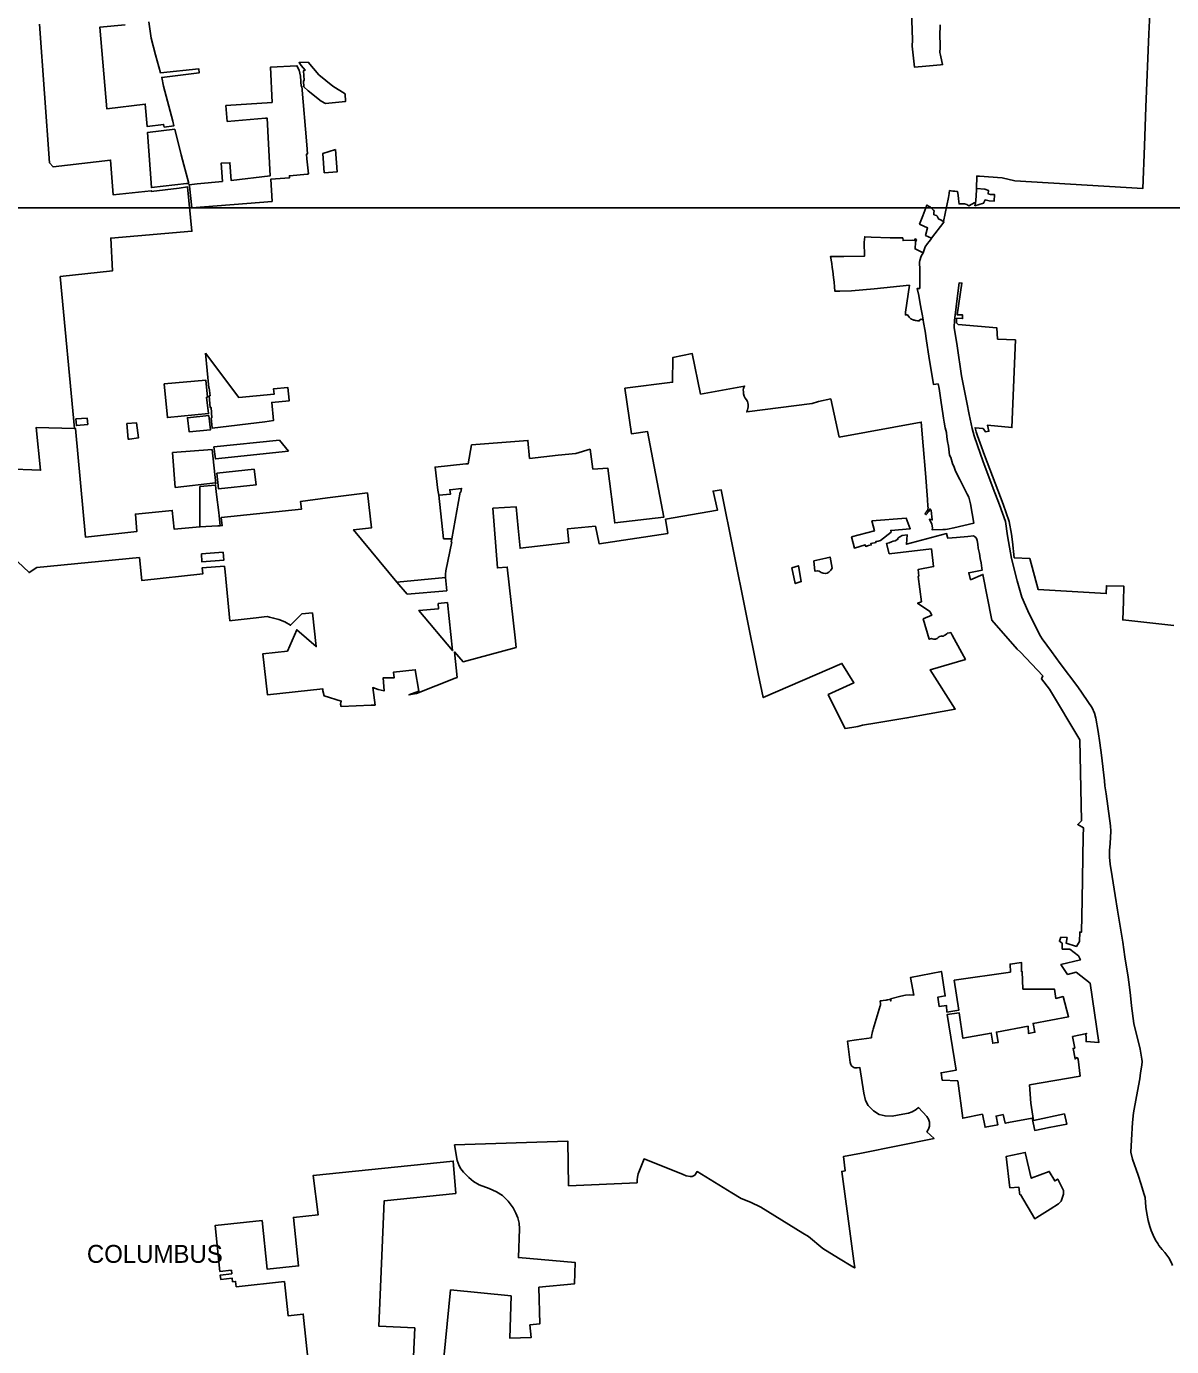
# Model space of a CAD drawing. Extents: x 1674899 to 2057726, y 653888 to 988278.
# Drawn here: x 1771787 to 1803723, y 730859 to 767682 of the extents above; entities that cross this region are included whole.
import ezdxf

# ---------------------------------------------------------------- set-up
doc = ezdxf.new("R2010")
doc.units = 0
for name, color, linetype in [('GM_X_Corporation', 7, 'Continuous'), ('GM_X_Corporation_Text', 7, 'Continuous'), ('SH_Named_Boundary', 7, 'Continuous')]:
    doc.layers.add(name, color=color, linetype=linetype)

msp = doc.modelspace()

# ---------------------------------------------------------------- linework, layer by layer
at = {"layer": 'GM_X_Corporation'}
for points in [[(1770221, 755380), (1772181, 755302), (1772057, 756492), (1773124, 756470), (1773153, 756469), (1773437, 753432), (1774866, 753591), (1774825, 754079), (1775856, 754180), (1775906, 753660), (1776624, 753722), (1777130, 753751), (1777182, 753756), (1777187, 753756), (1777192, 753756), (1777203, 753757), (1777227, 753759), (1777248, 753761), (1777222, 753980), (1779459, 754220), (1779429, 754427), (1780187, 754529), (1781295, 754669), (1781415, 753697), (1780909, 753642), (1782119, 752179), (1782408, 751849), (1783508, 751942), (1783479, 752309), (1783471, 752408), (1783484, 752497), (1783649, 753302), (1783633, 753301), (1783649, 753390), (1783882, 754688), (1783903, 754693), (1783921, 754795), (1783593, 754757), (1783615, 754639), (1783284, 754607), (1783265, 754751), (1783184, 755392), (1784040, 755478), (1784107, 755485), (1784200, 756011), (1785774, 756133), (1785821, 755634), (1786620, 755722), (1787106, 755772), (1787508, 755887), (1787585, 755334), (1787998, 755364), (1788193, 753835), (1789563, 753993), (1789108, 756382), (1788659, 756318), (1788479, 757590), (1789807, 757755), (1789818, 758450), (1790355, 758555), (1790586, 757428), (1791817, 757651), (1791798, 757614), (1791788, 757587), (1791780, 757546), (1791782, 757487), (1791788, 757438), (1791805, 757364), (1791835, 757312), (1791867, 757269), (1791892, 757218), (1791908, 757179), (1791915, 757135), (1791911, 757075), (1791904, 757024), (1791892, 756983), (1791876, 756928), (1793703, 757167), (1793873, 757222), (1794220, 757291), (1794455, 756226), (1796742, 756644), (1796798, 755979), (1796859, 755222), (1796915, 754482), (1796927, 754304), (1796931, 754250), (1796929, 754213), (1796912, 754181), (1796877, 754133), (1796843, 754097), (1796883, 754064), (1796952, 754150), (1796983, 754223), (1797022, 754175), (1797047, 753919), (1796968, 753934), (1797035, 753796), (1797053, 753693), (1797049, 753638), (1797341, 753647), (1797421, 753653), (1797474, 753661), (1797655, 753696), (1798210, 753829), (1798116, 754362), (1798071, 754553), (1798026, 754636), (1797814, 755043), (1797693, 755276), (1797657, 755384), (1797616, 755493), (1797564, 755654), (1797534, 755727), (1797500, 755975), (1797475, 756104), (1797452, 756237), (1797445, 756358), (1797413, 756483), (1797382, 756639), (1797361, 756753), (1797349, 756823), (1797285, 757257), (1797242, 757581), (1797210, 757710), (1797087, 757691), (1796955, 758481), (1796885, 758915), (1796847, 759179), (1796806, 759422), (1796792, 759498), (1796775, 759605), (1796742, 759796), (1796699, 760004), (1796671, 760173), (1796631, 760376), (1796701, 760373), (1796705, 760456), (1796703, 760557), (1796705, 760694), (1796699, 760891), (1796690, 761106), (1796705, 761148), (1796741, 761269), (1796792, 761362), (1796847, 761530), (1796917, 761623), (1796961, 761681), (1797003, 761733), (1797028, 761773), (1797374, 762223), (1797363, 762240), (1797453, 762684), (1797500, 762912), (1797522, 763017), (1797533, 763101), (1797623, 763091), (1797676, 763083), (1797721, 763081), (1797757, 763077), (1797761, 763030), (1797770, 762968), (1797782, 762885), (1797788, 762787), (1797797, 762730), (1797881, 762730), (1797948, 762730), (1798010, 762716), (1798071, 762682), (1798232, 762768), (1798251, 762763), (1798259, 762760), (1798240, 762681), (1798478, 762748), (1798523, 762842), (1798636, 762814), (1798776, 762808), (1798789, 762992), (1798672, 762998), (1798612, 763008), (1798618, 763105), (1798514, 763138), (1798285, 763163), (1798291, 763505), (1798362, 763501), (1799001, 763458), (1799354, 763375), (1802922, 763165), (1802964, 764353), (1803002, 765433), (1803091, 767476), (1803123, 768218)], [(1803123, 768218), (1803091, 767476), (1803002, 765433), (1802964, 764353), (1802922, 763165), (1799354, 763375), (1799001, 763458), (1798362, 763501), (1798291, 763505), (1798285, 763163), (1798285, 763121), (1798261, 762817), (1798251, 762763), (1798232, 762768), (1798071, 762682), (1798010, 762716), (1797948, 762730), (1797881, 762730), (1797797, 762730), (1797788, 762787), (1797782, 762885), (1797770, 762968), (1797761, 763030), (1797757, 763077), (1797721, 763081), (1797676, 763083), (1797623, 763091), (1797533, 763101), (1797522, 763017), (1797500, 762912), (1797453, 762684), (1797363, 762240), (1797328, 762261), (1797285, 762286), (1797235, 762306), (1797215, 762337), (1797189, 762393), (1797166, 762407), (1797095, 762431), (1797095, 762464), (1797096, 762492), (1797098, 762526), (1797079, 762553), (1797035, 762603), (1796999, 762638), (1796960, 762661), (1796901, 762700), (1796787, 762397), (1796734, 762256), (1796695, 762167), (1796714, 762158), (1796917, 762062), (1796864, 761847), (1797028, 761773), (1797003, 761733), (1796961, 761681), (1796917, 761623), (1796847, 761530), (1796792, 761362), (1796570, 761475), (1796586, 761667), (1796609, 761738), (1796566, 761754), (1796559, 761715), (1796509, 761719), (1796236, 761708), (1796228, 761782), (1795879, 761782), (1795343, 761802), (1795167, 761813), (1795148, 761662), (1795159, 761273), (1794583, 761261), (1794207, 761261), (1794244, 761065), (1794262, 760959), (1794275, 760853), (1794298, 760683), (1794310, 760545), (1794319, 760417), (1794336, 760293), (1794473, 760293), (1794798, 760307), (1795429, 760358), (1796412, 760460), (1796307, 759710), (1796302, 759633), (1796357, 759638), (1796408, 759574), (1796455, 759524), (1796534, 759493), (1796552, 759487), (1796578, 759477), (1796599, 759476), (1796640, 759471), (1796685, 759467), (1796706, 759495), (1796737, 759516), (1796763, 759510), (1796792, 759498), (1796806, 759422), (1796847, 759179), (1796885, 758915), (1796955, 758481), (1797087, 757691), (1797210, 757710), (1797242, 757581), (1797285, 757257), (1797349, 756823), (1797361, 756753), (1797382, 756639), (1797413, 756483), (1797445, 756358), (1797452, 756237), (1797475, 756104), (1797500, 755975), (1797534, 755727), (1797564, 755654), (1797616, 755493), (1797657, 755384), (1797693, 755276), (1797814, 755043), (1798026, 754636), (1798071, 754553), (1798116, 754362), (1798210, 753829), (1797655, 753696), (1797474, 753661), (1797421, 753653), (1797341, 753647), (1797049, 753638), (1797053, 753693), (1797035, 753796), (1796968, 753934), (1797047, 753919), (1797022, 754175), (1796983, 754223), (1796952, 754150), (1796883, 754064), (1796843, 754097), (1796877, 754133), (1796912, 754181), (1796929, 754213), (1796931, 754250), (1796927, 754304), (1796915, 754482), (1796859, 755222), (1796798, 755979), (1796742, 756644), (1794455, 756226), (1794220, 757291), (1793873, 757222), (1793703, 757167), (1791876, 756928), (1791892, 756983), (1791904, 757024), (1791911, 757075), (1791915, 757135), (1791908, 757179), (1791892, 757218), (1791867, 757269), (1791835, 757312), (1791805, 757364), (1791788, 757438), (1791782, 757487), (1791780, 757546), (1791788, 757587), (1791798, 757614), (1791817, 757651), (1790586, 757428), (1790355, 758555), (1789818, 758450), (1789807, 757755), (1788479, 757590), (1788659, 756318), (1789108, 756382), (1789563, 753993), (1788193, 753835), (1787998, 755364), (1787585, 755334), (1787508, 755887), (1787106, 755772), (1786620, 755722), (1785821, 755634), (1785774, 756133), (1784200, 756011), (1784107, 755485), (1784040, 755478), (1783184, 755392), (1783265, 754751), (1783284, 754607), (1783421, 753391), (1783649, 753390), (1783633, 753301), (1783649, 753302), (1783484, 752497), (1783471, 752408), (1783479, 752309), (1782119, 752179), (1780909, 753642), (1781415, 753697), (1781295, 754669), (1780187, 754529), (1779429, 754427), (1779459, 754220), (1777222, 753980), (1777248, 753761), (1777227, 753759), (1777203, 753757), (1777192, 753756), (1777150, 754125), (1777091, 754630), (1777072, 754794), (1777061, 754886), (1776626, 754848), (1776624, 753722), (1775906, 753660), (1775856, 754180), (1774825, 754079), (1774866, 753591), (1773437, 753432), (1773153, 756469), (1773124, 756470), (1772730, 760702), (1774189, 760869), (1774141, 761779), (1776402, 761968), (1776281, 763207), (1776046, 763174), (1775267, 763080), (1775267, 763099), (1774207, 762980), (1774134, 763952), (1772529, 763765), (1772435, 763880), (1772154, 767744)], [(1796465, 768373), (1796499, 767312), (1796490, 767130), (1796555, 766544), (1796870, 766570), (1797279, 766609), (1797338, 766615), (1797312, 766701), (1797277, 766882), (1797259, 766955), (1797271, 767095), (1797270, 767147), (1797268, 767221), (1797269, 767275), (1797264, 767337), (1797264, 767536), (1797272, 767608), (1797272, 767726)], [(1774541, 767725), (1773835, 767662), (1774031, 765380), (1775103, 765517), (1775155, 764887), (1775613, 764948), (1775632, 764875), (1775901, 764913), (1775868, 765038), (1775612, 766018), (1775562, 766261), (1776602, 766385), (1776595, 766499), (1775530, 766385), (1775389, 766892), (1775267, 767351), (1775201, 767808)], [(1803782, 750969), (1802362, 751127), (1802386, 751643), (1802395, 752068), (1801904, 752081), (1801902, 751864), (1800004, 751976), (1799768, 752839), (1799337, 752860), (1799288, 753301), (1799259, 753517), (1799195, 753873), (1799030, 754356), (1798507, 755721), (1798384, 756061), (1798314, 756259), (1798276, 756372), (1798244, 756489), (1798467, 756467), (1798529, 756374), (1798628, 756388), (1798591, 756564), (1799270, 756493), (1799367, 758939), (1798870, 758963), (1798849, 759277), (1797769, 759368), (1797722, 759416), (1797725, 759540), (1797893, 759534), (1797896, 759634), (1797741, 759640), (1797877, 760524), (1797803, 760530), (1797766, 760246), (1797665, 759477), (1797660, 759284), (1797739, 758775), (1797865, 757935), (1798015, 757195), (1798077, 756860), (1798161, 756466), (1798219, 756258), (1798311, 755995), (1798463, 755566), (1798749, 754795), (1798922, 754336), (1799095, 753877), (1799143, 753477), (1799257, 752840), (1799415, 752215), (1799549, 751765), (1799716, 751380), (1799745, 751315), (1800064, 750675), (1800110, 750597), (1800378, 750247), (1800618, 749910), (1801104, 749259), (1801506, 748678), (1801573, 748527), (1801614, 748387), (1801674, 748018), (1801725, 747703), (1801772, 747359), (1801849, 746636), (1801866, 746504), (1801900, 746273), (1801946, 745930), (1802019, 745382), (1802026, 745240), (1802006, 744894), (1801995, 744699), (1801990, 744508), (1802010, 744316), (1802068, 743972), (1802151, 743437), (1802219, 743032), (1802361, 742140), (1802422, 741731), (1802510, 741161), (1802552, 740884), (1802579, 740653), (1802606, 740359), (1802669, 739874), (1802844, 739158), (1802892, 738875), (1802901, 738809), (1802896, 738710), (1802860, 738491), (1802839, 738324), (1802746, 737839), (1802664, 737376), (1802630, 737112), (1802604, 736629), (1802584, 736279), (1802630, 736088), (1802792, 735637), (1802877, 735381), (1802950, 735133), (1802983, 735015), (1803009, 734748), (1803029, 734574), (1803069, 734376), (1803118, 734213), (1803153, 734096), (1803206, 733969), (1803274, 733830), (1803337, 733732), (1803368, 733683), (1803458, 733568), (1803531, 733484), (1803645, 733338), (1803723, 733195), (1803753, 733119)], [(1783429, 730546), (1783614, 732439), (1785305, 732274), (1785265, 731095), (1785864, 731116), (1785829, 731462), (1786109, 731495), (1786081, 732516), (1787068, 732606), (1787086, 733205), (1785506, 733341), (1785537, 734146), (1785530, 734302), (1785490, 734451), (1785435, 734577), (1785357, 734729), (1785223, 734911), (1785067, 735075), (1784895, 735179), (1784693, 735269), (1784413, 735373), (1784257, 735460), (1784128, 735574), (1784041, 735657), (1783980, 735727), (1783903, 735814), (1783857, 735903), (1783797, 736047), (1783729, 736484), (1786883, 736592), (1786907, 735343), (1788818, 735431), (1788815, 735475), (1788820, 735508), (1788829, 735580), (1788851, 735682), (1788920, 735864), (1789012, 736092), (1790098, 735655), (1790189, 735623), (1790305, 735599), (1790352, 735602), (1790432, 735643), (1790492, 735739), (1791458, 735151), (1791718, 734992), (1791982, 734884), (1792270, 734745), (1793442, 734023), (1793602, 733927), (1793997, 733597), (1794437, 733326), (1794832, 733084), (1794885, 733054), (1794861, 733242), (1794699, 734497), (1794545, 735602), (1794525, 735745), (1794624, 735763), (1794570, 736161), (1795072, 736254), (1797098, 736664), (1796898, 736851), (1796940, 736926), (1796970, 737010), (1796975, 737119), (1796947, 737199), (1796900, 737273), (1796669, 737527), (1796601, 737474), (1796487, 737408), (1796389, 737373), (1796226, 737341), (1795929, 737286), (1795732, 737292), (1795571, 737335), (1795407, 737432), (1795257, 737587), (1795185, 737723), (1795137, 737924), (1795029, 738645), (1794951, 738634), (1794915, 738633), (1794889, 738637), (1794863, 738646), (1794833, 738663), (1794810, 738682), (1794791, 738704), (1794776, 738730), (1794767, 738751), (1794761, 738782), (1794687, 739379), (1794932, 739413), (1795353, 739472), (1795356, 739509), (1795364, 739564), (1795371, 739604), (1795380, 739643), (1795389, 739677), (1795400, 739714), (1795598, 740361), (1795600, 740370), (1795602, 740377), (1795603, 740384), (1795604, 740394), (1795605, 740401), (1795605, 740409), (1795604, 740415), (1795603, 740425), (1795596, 740483), (1795595, 740488), (1795593, 740491), (1795622, 740496), (1795614, 740501), (1795603, 740504), (1795756, 740523), (1795769, 740526), (1795782, 740529), (1795795, 740531), (1795811, 740534), (1795843, 740540), (1795853, 740541), (1795862, 740540), (1795869, 740537), (1795876, 740533), (1795883, 740527), (1795887, 740521), (1795889, 740516), (1795892, 740494), (1795895, 740520), (1795894, 740530), (1795892, 740542), (1795888, 740563), (1796176, 740637), (1796307, 740663), (1796408, 740671), (1796532, 740659), (1796442, 741158), (1797302, 741323), (1797412, 740638), (1797207, 740606), (1797242, 740342), (1797444, 740374), (1797459, 740191), (1797786, 740238), (1797664, 741078), (1799228, 741305), (1799220, 741530), (1799534, 741576), (1799542, 741316), (1799558, 741318), (1799575, 740830), (1800457, 740830), (1800493, 740571), (1800699, 740622), (1800850, 740057), (1799860, 739872), (1799911, 739627), (1799731, 739593), (1799723, 739796), (1798839, 739630), (1798886, 739338), (1798799, 739334), (1798737, 739318), (1798692, 739605), (1797903, 739457), (1797796, 740170), (1797469, 740123), (1797713, 738565), (1797296, 738495), (1797323, 738291), (1797759, 738271), (1797898, 737226), (1798449, 737341), (1798524, 736975), (1798882, 737045), (1798827, 737288), (1799026, 737330), (1799082, 737088), (1799179, 737105), (1799836, 737231), (1799906, 736887), (1800305, 736970), (1800508, 737011), (1800801, 737062), (1800735, 737351), (1799874, 737168), (1799795, 737644), (1799761, 738159), (1801173, 738406), (1801119, 738880), (1801089, 738921), (1801071, 738909), (1801032, 738885), (1800975, 739174), (1801024, 739183), (1800963, 739506), (1801356, 739592), (1801351, 739589), (1801346, 739585), (1801343, 739582), (1801339, 739577), (1801335, 739571), (1801333, 739567), (1801331, 739562), (1801330, 739557), (1801329, 739549), (1801329, 739546), (1801330, 739540), (1801331, 739535), (1801332, 739530), (1801335, 739524), (1801342, 739514), (1801343, 739495), (1801345, 739462), (1801344, 739422), (1801342, 739404), (1801341, 739386), (1801338, 739365), (1801694, 739338), (1801449, 740993), (1801066, 741306), (1800821, 741241), (1800636, 741516), (1801179, 741642), (1801130, 741758), (1800882, 741940), (1800674, 741946), (1800674, 742111), (1800596, 742166), (1800636, 742276), (1800810, 742267), (1800786, 742107), (1801071, 742020), (1801125, 742113), (1801155, 742156), (1801160, 742422), (1801214, 742421), (1801229, 743323), (1801259, 745100), (1801263, 745329), (1801105, 745419), (1801209, 745526), (1801161, 747779), (1800318, 749198), (1800097, 749485), (1800128, 749567), (1799507, 750229), (1799412, 750316), (1798706, 751120), (1798462, 752398), (1798117, 752249), (1798068, 752442), (1798442, 752517), (1798433, 752573), (1798413, 752720), (1798384, 752837), (1798362, 752976), (1798333, 753132), (1798318, 753240), (1798305, 753344), (1798285, 753395), (1798262, 753427), (1798227, 753454), (1798198, 753471), (1798041, 753453), (1797723, 753424), (1797479, 753412), (1797476, 753439), (1797450, 753537), (1796330, 753237), (1796353, 753497), (1796210, 753481), (1796143, 753449), (1796092, 753406), (1796093, 753377), (1796014, 753336), (1795954, 753326), (1795913, 753303), (1795847, 753280), (1795773, 753260), (1795848, 752973), (1797026, 753110), (1797087, 752615), (1796652, 752533), (1796671, 752350), (1796658, 752339), (1796746, 751636), (1796638, 751592), (1796977, 751366), (1797033, 751257), (1796799, 751155), (1796966, 750588), (1797025, 750609), (1797047, 750598), (1797092, 750589), (1797136, 750587), (1797160, 750598), (1797188, 750613), (1797217, 750636), (1797237, 750657), (1797253, 750666), (1797285, 750676), (1797298, 750681), (1797320, 750675), (1797341, 750673), (1797359, 750677), (1797381, 750690), (1797421, 750713), (1797454, 750740), (1797471, 750760), (1797531, 750772), (1797564, 750776), (1797603, 750700), (1797878, 750206), (1797975, 750025), (1796995, 749737), (1797690, 748639), (1796961, 748506), (1796340, 748394), (1795502, 748255), (1795107, 748192), (1794974, 748159), (1794804, 748124), (1794616, 748095), (1794574, 748180), (1794147, 749043), (1794865, 749373), (1794531, 749912), (1792336, 748961), (1792198, 749626), (1791164, 754755), (1790938, 754719), (1791056, 754185), (1789610, 753934), (1789671, 753539), (1787760, 753249), (1787654, 753742), (1786874, 753665), (1786906, 753382), (1786916, 753283), (1786443, 753233), (1785553, 753125), (1785499, 753683), (1785442, 754285), (1784796, 754242), (1784920, 752578), (1785195, 752599), (1785416, 750625), (1785444, 750360), (1783963, 749959), (1783729, 750233), (1783799, 749524), (1783741, 749503), (1782666, 749072), (1782456, 749036), (1782732, 749144), (1782633, 749738), (1782024, 749670), (1782040, 749512), (1781732, 749512), (1781763, 749148), (1781598, 749189), (1781445, 749241), (1781509, 748753), (1781398, 748749), (1780567, 748710), (1780546, 748779), (1780565, 748866), (1780090, 749006), (1780055, 749146), (1780051, 749207), (1778506, 749039), (1778382, 750183), (1779068, 750252), (1779327, 750854), (1779872, 750383), (1779761, 751324), (1779466, 751295), (1779153, 750981), (1778998, 751072), (1778827, 751143), (1778680, 751179), (1778562, 751205), (1778501, 751220), (1778415, 751215), (1778192, 751189), (1777521, 751114), (1777461, 751105), (1777328, 752466), (1777311, 752624), (1776693, 752582), (1776711, 752414), (1775007, 752225), (1774938, 752864), (1772077, 752586), (1771864, 752450), (1769725, 754457)], [(1779654, 730364), (1779507, 731764), (1779085, 731719), (1778983, 732673), (1777637, 732530), (1777622, 732677), (1777536, 732668), (1777525, 732768), (1777207, 732734), (1777194, 732855), (1777513, 732889), (1777502, 732988), (1777184, 732955), (1777049, 734232), (1778358, 734372), (1778503, 733014), (1779377, 733108), (1779233, 734463), (1779925, 734537), (1779785, 735635), (1783690, 736031), (1783761, 735131), (1781764, 734921), (1781619, 731424), (1782618, 731382), (1782584, 730581)]]:
    msp.add_lwpolyline(points, dxfattribs=at)
for points in [[(1779526, 765996), (1779649, 765886), (1780007, 765600), (1780127, 765528), (1780688, 765588), (1780677, 765797), (1780336, 766018), (1779945, 766331), (1779640, 766689), (1779392, 766675), (1779449, 766592), (1779558, 766458), (1779517, 766446), (1779531, 766180), (1779519, 766152)], [(1777350, 765480), (1777390, 765033), (1778456, 765121), (1778497, 765124), (1778588, 763518), (1777500, 763383), (1777464, 763881), (1777215, 763863), (1777251, 763358), (1776548, 763289), (1776325, 763267), (1776334, 763222), (1776405, 762617), (1778638, 762800), (1778601, 763421), (1779128, 763459), (1779121, 763518), (1779630, 763563), (1779650, 763567), (1779608, 763988), (1779595, 764118), (1779623, 764127), (1779603, 764375), (1779472, 766012), (1779452, 766010), (1779430, 766292), (1779392, 766458), (1779331, 766585), (1778592, 766543), (1778640, 765564)], [(1775930, 764813), (1775164, 764721), (1775275, 763188), (1776254, 763296), (1776316, 763302), (1776105, 764098)], [(1780404, 764245), (1780055, 764138), (1780095, 763598), (1780455, 763628)], [(1776781, 758571), (1776874, 757598), (1776884, 757599), (1776909, 757379), (1776884, 757376), (1776915, 757049), (1776937, 757054), (1776962, 756765), (1776941, 756764), (1776966, 756480), (1778434, 756650), (1778682, 756690), (1778628, 757192), (1779114, 757236), (1779113, 757254), (1779078, 757609), (1778681, 757577), (1778697, 757425), (1777708, 757333)], [(1775632, 757715), (1775719, 756770), (1776867, 756883), (1776810, 757337), (1776839, 757343), (1776787, 757819)], [(1773167, 756733), (1773180, 756550), (1773499, 756580), (1773477, 756755)], [(1776879, 756830), (1776278, 756765), (1776322, 756377), (1776922, 756430)], [(1774587, 756604), (1774629, 756166), (1774663, 756170), (1774909, 756203), (1774860, 756623)], [(1779096, 755830), (1778843, 756143), (1777018, 755954), (1777056, 755620)], [(1776970, 755885), (1775862, 755797), (1775938, 754823), (1777065, 754950), (1777068, 754919)], [(1777098, 755224), (1777144, 754785), (1778199, 754896), (1778137, 755331)], [(1794796, 753442), (1794876, 753131), (1795181, 753219), (1795192, 753180), (1795272, 753203), (1795346, 753220), (1795335, 753259), (1795480, 753291), (1795474, 753312), (1795544, 753328), (1795606, 753339), (1795899, 753577), (1795891, 753624), (1796434, 753669), (1796318, 753969), (1795366, 753888), (1795438, 753609)], [(1776671, 752975), (1776681, 752746), (1777291, 752794), (1777271, 753017)], [(1793745, 752771), (1793775, 752489), (1793787, 752492), (1793842, 752499), (1793897, 752486), (1793951, 752453), (1794009, 752431), (1794065, 752420), (1794115, 752433), (1794167, 752458), (1794222, 752514), (1794260, 752570), (1794199, 752878), (1794082, 752848)], [(1793137, 752583), (1793226, 752140), (1793393, 752195), (1793317, 752638)], [(1783531, 751616), (1783273, 751584), (1783278, 751434), (1782734, 751391), (1783671, 750271)], [(1799215, 735290), (1799463, 735307), (1799493, 735096), (1799508, 735100), (1799905, 734427), (1799964, 734461), (1800338, 734694), (1800572, 734842), (1800640, 734911), (1800676, 734997), (1800706, 735114), (1800712, 735217), (1800549, 735530), (1800463, 735480), (1800309, 735744), (1799811, 735556), (1799640, 736275), (1799108, 736159)]]:
    msp.add_lwpolyline(points, close=True, dxfattribs=at)
at = {"layer": 'SH_Named_Boundary'}
msp.add_lwpolyline([(1741253, 762626), (1916253, 762626), (1916253, 897626), (1741253, 897626)], close=True, dxfattribs=at)

# ---------------------------------------------------------------- texts
at = {"layer": 'GM_X_Corporation_Text'}
msp.add_text('COLUMBUS', height=500, rotation=0, dxfattribs=at).set_placement((1773474, 733195))

doc.saveas('drawing.dxf')
